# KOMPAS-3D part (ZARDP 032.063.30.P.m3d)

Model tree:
1. Плоскость XY
2. Плоскость ZX
3. Плоскость ZY
4. Ось X
5. Ось Y
6. Ось Z
7. Начало координат
8. Операция без истории:2

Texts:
  133 1 134 1 135 1 136 0 50 1|SPDS|133 1 134 1 135 1 136 0 50 1
  125 1 126 1 127 1 128 0 50 1|SPDS|125 1 126 1 127 1 128 0 50 1
  129 1 130 1 131 1 132 0 50 1|SPDS|129 1 130 1 131 1 132 0 50 1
